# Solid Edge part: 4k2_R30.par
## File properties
Author: Türk
Template: Iso Part.par
Last saved by: Türk
Revision: 6
Application: Solid Edge
Accuracy: 0,990
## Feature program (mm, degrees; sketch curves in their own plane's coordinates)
pattern "PatternOccurrence_1"  XOffset = 9.7297 deg
pattern "PatternOccurrence_2"  XCount = 37; XOffset = 9.7297 deg
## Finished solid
Body 1: solid body, 225 faces, 668 edges, 444 vertices.
  Faces by surface: plane 150, cylinder 75
  Edges by curve: line 518, circle 150
Bounding box of the edges (mm): 67.976 x 30.000 x 67.920, from (-33.9882, 0, -33.9196) to (33.9882, 30, 34).
Cylindrical faces by radius (mm): R14 x1, R30 x37, R34 x37
Planar faces by outward normal: +y 1, -y 1, -z 2, oblique 146
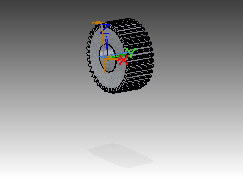
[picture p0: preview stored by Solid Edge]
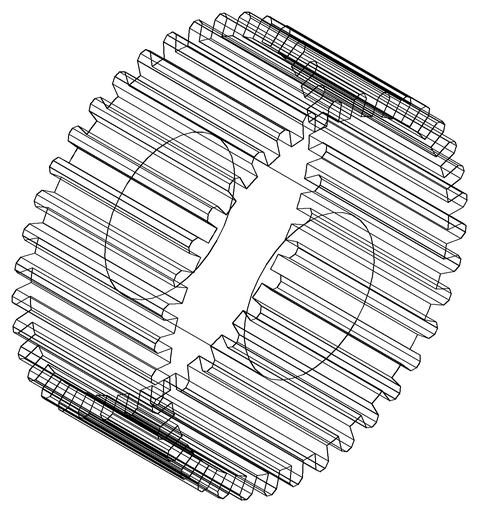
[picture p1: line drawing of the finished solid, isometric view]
